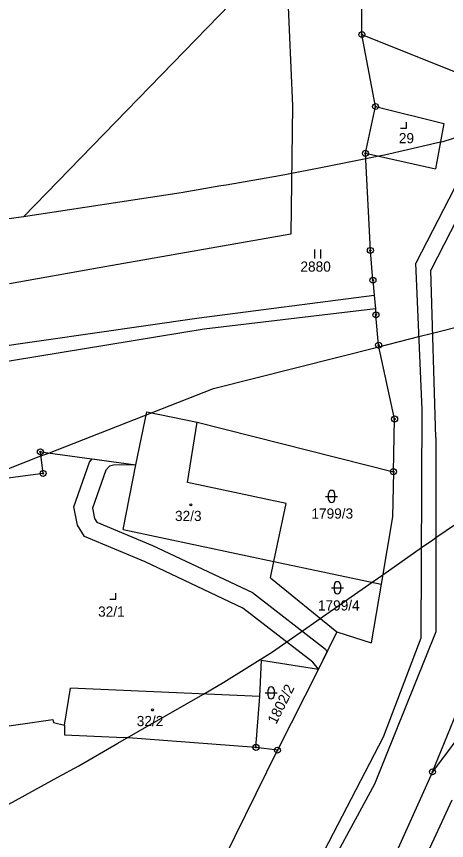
# Model space of a CAD drawing. Extents: x -546762 to -540209, y -1046851 to -1035694.
# Drawn here: x -542616.2 to -542544.6, y -1039106.5 to -1038969.2 of the extents above; entities that cross this region are included whole.
import ezdxf

# ---------------------------------------------------------------- set-up
doc = ezdxf.new("R2010")
doc.units = 0
for name, color, linetype in [('Vrstva 1', 7, 'Continuous'), ('Vrstva 18', 7, 'Continuous'), ('Vrstva 19', 7, 'Continuous'), ('Vrstva 24', 7, 'Continuous'), ('Vrstva 25', 7, 'Continuous'), ('Vrstva 3', 7, 'Continuous'), ('Vrstva 30', 7, 'Continuous'), ('Vrstva 37', 7, 'Continuous'), ('Vrstva 52', 7, 'Continuous')]:
    doc.layers.add(name, color=color, linetype=linetype)

msp = doc.modelspace()

# ---------------------------------------------------------------- linework, layer by layer
at = {"layer": 'Vrstva 1'}
for p, q in [((-542558.66, -1038972.17), (-542534.93, -1038981.72)), ((-542587.7, -1039046.83), (-542586.11, -1039036.79)), ((-542598.43, -1039054.64), (-542596.35, -1039043.9)), ((-542553.4, -1039045.02), (-542553.56, -1039052.53)), ((-542565.87, -1039077.92), (-542572.73, -1039091.43)), ((-542608.22, -1039087.23), (-542607.23, -1039081.11)), ((-542576.32, -1039090.96), (-542575.66, -1039082.49))]:
    msp.add_line(p, q, dxfattribs=at)
for points in [[(-542558.66, -1038972.17), (-542558.71, -1038963.05)], [(-542571.05, -1038964.98), (-542570.2, -1038984.03)], [(-542556.39, -1038984.17), (-542558.66, -1038972.17)], [(-542534.93, -1038981.72), (-542549.69, -1039010.29)], [(-542570.2, -1038984.03), (-542570.53, -1039005.41)], [(-542558.07, -1038991.96), (-542556.39, -1038984.17)], [(-542556.39, -1038984.17), (-542544.99, -1038987.01)], [(-542532.92, -1038983.73), (-542547.19, -1039011.41)], [(-542544.99, -1038987.01), (-542546.39, -1038994.57)], [(-542557.25, -1039008.15), (-542558.07, -1038991.96)], [(-542558.07, -1038991.96), (-542546.39, -1038994.57)], [(-542570.53, -1039005.41), (-542602.46, -1039011.07)], [(-542556.82, -1039013.11), (-542557.25, -1039008.15)], [(-542548.63, -1039034.66), (-542549.69, -1039010.29)], [(-542602.46, -1039011.07), (-542617.4, -1039013.69)], [(-542546.34, -1039039.31), (-542547.19, -1039011.41)], [(-542556.82, -1039013.11), (-542556.6, -1039015.59)], [(-542585.8, -1039019.36), (-542556.6, -1039015.59)], [(-542556.6, -1039015.59), (-542556.4, -1039017.87)], [(-542556.4, -1039017.87), (-542584.96, -1039021.25)], [(-542556.4, -1039017.87), (-542556.31, -1039018.88)], [(-542555.87, -1039023.93), (-542556.31, -1039018.88)], [(-542664.68, -1039030.7), (-542585.8, -1039019.36)], [(-542584.96, -1039021.25), (-542660.73, -1039033.69)], [(-542553.21, -1039036.23), (-542555.87, -1039023.93)], [(-542596.35, -1039043.9), (-542594.52, -1039035.03)], [(-542594.52, -1039035.03), (-542586.11, -1039036.79)], [(-542548.76, -1039072.73), (-542548.63, -1039034.66)], [(-542553.4, -1039045.02), (-542553.21, -1039036.23)], [(-542586.11, -1039036.79), (-542553.4, -1039045.02)], [(-542546.34, -1039039.31), (-542546.31, -1039071.7)], [(-542611.79, -1039045.31), (-542612.24, -1039041.71)], [(-542612.24, -1039041.71), (-542596.35, -1039043.9)], [(-542611.79, -1039045.31), (-542626.45, -1039047.29)], [(-542571.28, -1039050.31), (-542587.7, -1039046.83)], [(-542573.33, -1039059.96), (-542571.28, -1039050.31)], [(-542553.56, -1039052.53), (-542555.45, -1039063.75)], [(-542598.43, -1039054.64), (-542573.33, -1039059.96)], [(-542573.91, -1039062.69), (-542573.33, -1039059.96)], [(-542573.33, -1039059.96), (-542555.45, -1039063.75)], [(-542573.91, -1039062.69), (-542562.86, -1039071.68)], [(-542555.45, -1039063.75), (-542557.1, -1039073.53)], [(-542562.86, -1039071.68), (-542565.87, -1039077.92)], [(-542562.86, -1039071.68), (-542557.1, -1039073.53)], [(-542546.31, -1039071.7), (-542556.54, -1039097.11)], [(-542555.06, -1039089.2), (-542548.76, -1039072.73)], [(-542575.66, -1039082.49), (-542575.4, -1039076.43)], [(-542575.4, -1039076.43), (-542565.87, -1039077.92)], [(-542534.11, -1039077.92), (-542546.9, -1039095.04)], [(-542575.66, -1039082.49), (-542607.23, -1039081.11)], [(-542546.9, -1039095.04), (-542542.41, -1039084.04)], [(-542620.98, -1039087.89), (-542610.19, -1039086.31)], [(-542610.19, -1039086.31), (-542610.08, -1039086.82)], [(-542610.08, -1039086.82), (-542608.22, -1039087.23)], [(-542608.22, -1039087.23), (-542608.25, -1039088.85)], [(-542608.25, -1039088.85), (-542598.33, -1039089.33)], [(-542576.32, -1039090.96), (-542598.33, -1039089.33)], [(-542571.03, -1039119.9), (-542555.06, -1039089.2)], [(-542583.32, -1039112.96), (-542572.73, -1039091.43)], [(-542572.73, -1039091.43), (-542576.32, -1039090.96)], [(-542546.9, -1039095.04), (-542568.14, -1039142.17)], [(-542556.54, -1039097.11), (-542570.15, -1039122.19)], [(-542563.09, -1039141.89), (-542543.62, -1039099.68)]]:
    msp.add_lwpolyline(points, dxfattribs=at)
at = {"layer": 'Vrstva 24'}
for centre, radius in [((-542558.66, -1038972.17), 0.5), ((-542558.66, -1038972.17), 0.1), ((-542556.39, -1038984.17), 0.5), ((-542556.39, -1038984.17), 0.1), ((-542558.07, -1038991.96), 0.5), ((-542558.07, -1038991.96), 0.1), ((-542557.25, -1039008.15), 0.5), ((-542557.25, -1039008.15), 0.1), ((-542556.82, -1039013.11), 0.5), ((-542556.82, -1039013.11), 0.1), ((-542556.31, -1039018.88), 0.5), ((-542556.31, -1039018.88), 0.1), ((-542555.87, -1039023.93), 0.5), ((-542555.87, -1039023.93), 0.1), ((-542553.21, -1039036.23), 0.5), ((-542553.21, -1039036.23), 0.1), ((-542612.24, -1039041.71), 0.5), ((-542612.24, -1039041.71), 0.1), ((-542611.79, -1039045.31), 0.5), ((-542553.4, -1039045.02), 0.5), ((-542553.4, -1039045.02), 0.1), ((-542611.79, -1039045.31), 0.1), ((-542576.32, -1039090.96), 0.5), ((-542576.32, -1039090.96), 0.1), ((-542572.73, -1039091.43), 0.5), ((-542572.73, -1039091.43), 0.1), ((-542546.9, -1039095.04), 0.5), ((-542546.9, -1039095.04), 0.1)]:
    msp.add_circle(centre, radius, dxfattribs=at)
at = {"layer": 'Vrstva 25'}
for p, q in [((-542566.52, -1039009.48), (-542566.52, -1039007.98)), ((-542565.52, -1039009.48), (-542565.52, -1039007.98)), ((-542564.2, -1039049.64), (-542564.2, -1039048.64)), ((-542563.2, -1039048.64), (-542563.2, -1039049.64)), ((-542564.7, -1039049.14), (-542562.7, -1039049.14)), ((-542563.25, -1039064.85), (-542563.25, -1039063.85)), ((-542562.25, -1039063.85), (-542562.25, -1039064.85)), ((-542563.75, -1039064.35), (-542561.75, -1039064.35)), ((-542574.79, -1039081.88), (-542572.79, -1039081.88)), ((-542574.29, -1039082.38), (-542574.29, -1039081.38)), ((-542573.29, -1039081.38), (-542573.29, -1039082.38))]:
    msp.add_line(p, q, dxfattribs=at)
for points in [[(-542552.2, -1038987.75), (-542551.2, -1038987.75), (-542551.2, -1038986.75)], [(-542600.68, -1039066.24), (-542599.68, -1039066.24), (-542599.68, -1039065.24)]]:
    msp.add_lwpolyline(points, dxfattribs=at)
for centre in [(-542587.17, -1039050.54), (-542593.55, -1039084.72)]:
    msp.add_circle(centre, 0.175, dxfattribs=at)
for centre, start, end in [((-542563.7, -1039048.64), 0, 180), ((-542563.7, -1039049.64), 180, 0), ((-542562.75, -1039063.85), 0, 180), ((-542562.75, -1039064.85), 180, 0), ((-542573.79, -1039081.38), 0, 180), ((-542573.79, -1039082.38), 180, 0)]:
    msp.add_arc(centre, 0.5, start, end, dxfattribs=at)
at = {"layer": 'Vrstva 3'}
for points in [[(-542596.35, -1039043.9), (-542594.52, -1039035.03)], [(-542594.52, -1039035.03), (-542586.11, -1039036.79)], [(-542587.7, -1039046.83), (-542586.11, -1039036.79)], [(-542598.43, -1039054.64), (-542596.35, -1039043.9)], [(-542571.28, -1039050.31), (-542587.7, -1039046.83)], [(-542573.33, -1039059.96), (-542571.28, -1039050.31)], [(-542598.43, -1039054.64), (-542573.33, -1039059.96)], [(-542608.22, -1039087.23), (-542607.23, -1039081.11)], [(-542575.66, -1039082.49), (-542607.23, -1039081.11)], [(-542576.32, -1039090.96), (-542575.66, -1039082.49)], [(-542608.22, -1039087.23), (-542608.25, -1039088.85)], [(-542608.25, -1039088.85), (-542598.33, -1039089.33)], [(-542576.32, -1039090.96), (-542598.33, -1039089.33)]]:
    msp.add_lwpolyline(points, dxfattribs=at)
at = {"layer": 'Vrstva 30'}
for p, q in [((-542606.65, -1039050.9), (-542604.04, -1039043.42)), ((-542604.04, -1039043.42), (-542603.59, -1039042.9)), ((-542603.59, -1039042.9), (-542596.35, -1039043.9)), ((-542601.34, -1039044.78), (-542603.55, -1039051.12)), ((-542600.71, -1039044.11), (-542601.34, -1039044.78)), ((-542600.08, -1039043.91), (-542600.71, -1039044.11)), ((-542596.35, -1039043.9), (-542600.08, -1039043.91)), ((-542606.06, -1039053.93), (-542606.65, -1039050.9)), ((-542603.55, -1039051.12), (-542603.22, -1039052.81)), ((-542603.22, -1039052.81), (-542602.84, -1039053.43)), ((-542604.88, -1039055.83), (-542606.06, -1039053.93)), ((-542602.84, -1039053.43), (-542593.56, -1039057.32)), ((-542594.78, -1039060.06), (-542604.88, -1039055.83)), ((-542593.56, -1039057.32), (-542576.91, -1039065.16)), ((-542578.49, -1039067.74), (-542594.78, -1039060.06)), ((-542576.91, -1039065.16), (-542564.71, -1039074.61)), ((-542566.82, -1039076.77), (-542578.49, -1039067.74)), ((-542564.48, -1039075.04), (-542565.87, -1039077.92)), ((-542564.71, -1039074.61), (-542564.48, -1039075.04)), ((-542565.87, -1039077.92), (-542566.82, -1039076.77))]:
    msp.add_line(p, q, dxfattribs=at)
at = {"layer": 'Vrstva 37'}
for centre in [(-542587.17, -1039050.54), (-542593.55, -1039084.72)]:
    msp.add_circle(centre, 0.175, dxfattribs=at)
at = {"layer": 'Vrstva 52'}
for points in [[(-542615.06, -1039002.55), (-542578.66, -1038965.04)], [(-542483.1, -1038970.94), (-542487.85, -1038972.05), (-542490.34, -1038972.63), (-542491.48, -1038972.9), (-542497.05, -1038974.28), (-542501.12, -1038975.29), (-542508.32, -1038977.46), (-542511.88, -1038978.53), (-542520.84, -1038981.67), (-542532.94, -1038986.15), (-542534.41, -1038986.62), (-542538.06, -1038987.78), (-542545.19, -1038990.04), (-542545.57, -1038990.13), (-542554.9, -1038992.28), (-542555.82, -1038992.46), (-542558.02, -1038992.89), (-542565.77, -1038994.42), (-542572.37, -1038995.72), (-542581.27, -1038997.26), (-542582.15, -1038997.41), (-542588.8, -1038998.56)], [(-542588.8, -1038998.56), (-542615.06, -1039002.55)], [(-542615.06, -1039002.55), (-542628.9, -1039004.45), (-542639.51, -1039005.64), (-542647.72, -1039006.24), (-542656.54, -1039007.44), (-542665.91, -1039008.89), (-542676.07, -1039010.69), (-542686.37, -1039012.63), (-542700.12, -1039016.07), (-542712.51, -1039019.95), (-542720.49, -1039023.11), (-542724.61, -1039024.74), (-542737.76, -1039031.91), (-542752.54, -1039040.58), (-542760.09, -1039045.96)], [(-542717.88, -1039092.26), (-542701.9, -1039083.16), (-542695.52, -1039079.53), (-542688.07, -1039075.8), (-542667.82, -1039065.67), (-542661.43, -1039062.91), (-542640.66, -1039053.96), (-542630.18, -1039049.45), (-542626.36, -1039047.96), (-542623.7, -1039046.92), (-542612.15, -1039042.4), (-542611.03, -1039041.96), (-542583.39, -1039031.14), (-542555.81, -1039024.19), (-542549.16, -1039022.51), (-542546.87, -1039021.93), (-542541.38, -1039020.54), (-542516.43, -1039014.25), (-542510.98, -1039012.88), (-542509.42, -1039012.49), (-542495.82, -1039009.05), (-542490.94, -1039007.82)], [(-542619.15, -1039101.33), (-542609.31, -1039095.91), (-542605.86, -1039094.01), (-542599.32, -1039090.27), (-542592.56, -1039086.39), (-542585.08, -1039082.08), (-542581.66, -1039080.11), (-542573.57, -1039075.04), (-542565.59, -1039069.46), (-542556.95, -1039063.43), (-542555.19, -1039062.2), (-542548.71, -1039057.67), (-542546.83, -1039056.36), (-542546.32, -1039056.01), (-542541.32, -1039052.59)]]:
    msp.add_lwpolyline(points, dxfattribs=at)

# ---------------------------------------------------------------- texts
at = {"layer": 'Vrstva 18'}
for s, p in [('2880', (-542568.9, -1039011.69)), ('1799/3', (-542567.07, -1039052.84)), ('1799/4', (-542565.99, -1039068.15))]:
    msp.add_text(s, height=1.7, dxfattribs=at).set_placement(p)
msp.add_text('1802/2', height=1.7, rotation=63.435, dxfattribs=at).set_placement((-542572.95, -1039087.22))
at = {"layer": 'Vrstva 19'}
for s, p in [('29', (-542552.5, -1038990.29)), ('32/3', (-542589.81, -1039053.24)), ('32/1', (-542602.62, -1039069.18)), ('32/2', (-542596.18, -1039087.42))]:
    msp.add_text(s, height=1.7, dxfattribs=at).set_placement(p)

doc.saveas('drawing.dxf')
